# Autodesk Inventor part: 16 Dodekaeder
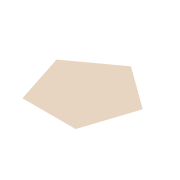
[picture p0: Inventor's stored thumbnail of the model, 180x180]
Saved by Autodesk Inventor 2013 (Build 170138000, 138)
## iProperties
Created: 2012-10
Part Number: 16 Dodekaeder
Material: Allgemein
Vendor: www.inventor-faq.de
Document SubType Name: Modeling
Designer: Administrator
Manufacturer: www.inventor-faq.de
Density: 1 g/cm^3
RuleStatus: InUse
AfterDocOpen0: inventorfaq
BeforeDocSave0: inventorfaq
Author: Administrator
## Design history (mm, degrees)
sketch "Skizze1"
  geometry: L1 (0, 8.507)-(8.09, 2.629); L2 (8.09, 2.629)-(5, -6.882); L3 (5, -6.882)-(-5, -6.882); L4 (-5, -6.882)-(-8.09, 2.629); L5 (-8.09, 2.629)-(0, 8.507); 2 further points
  constraints: 10 end point, 1 coincident, 1 horizontal, 11 other
  dimensions: "d0" = 10 distance of L2.end L3.end
feature "Umgrenzungsfläche1" sketch "Skizze1"
node "Fläche1"
